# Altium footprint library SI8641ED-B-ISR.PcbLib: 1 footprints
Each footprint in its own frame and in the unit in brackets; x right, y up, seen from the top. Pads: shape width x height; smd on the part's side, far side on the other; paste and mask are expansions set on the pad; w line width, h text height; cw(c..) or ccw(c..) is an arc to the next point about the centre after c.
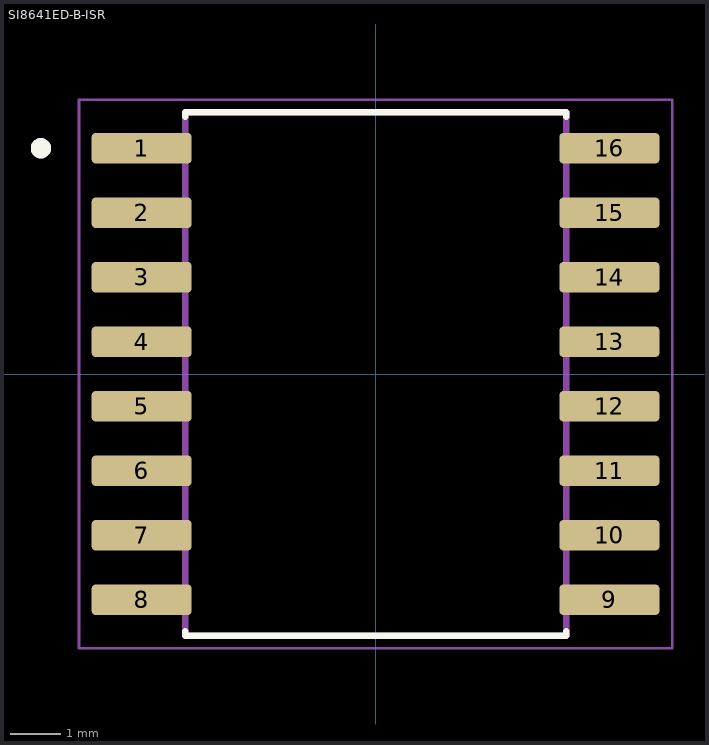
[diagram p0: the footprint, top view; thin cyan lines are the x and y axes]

## SI8641ED-B-ISR [mm]
pads (16):
  rrect25% 1.97x0.6 smd: 1(-4.605,4.445) 2(-4.605,3.175) 3(-4.605,1.905) 4(-4.605,0.635) 5(-4.605,-0.635) 6(-4.605,-1.905) 7(-4.605,-3.175) 8(-4.605,-4.445) 9(4.605,-4.445) 10(4.605,-3.175) 11(4.605,-1.905) 12(4.605,-0.635) 13(4.605,0.635) 14(4.605,1.905) 15(4.605,3.175) 16(4.605,4.445)
Top Overlay:
  circle w0.2: c-6.59,4.445 r0.1
  lines w0.127: -3.75,-5.065 -3.75,-5.15 3.75,-5.15 3.75,-5.065 ; -3.75,5.065 -3.75,5.15 3.75,5.15 3.75,5.065
Mechanical 13:
  circle w0.2: c-6.59,4.445 r0.1
  lines w0.127: -3.75,-5.15 -3.75,5.15 3.75,5.15 3.75,-5.15 -3.75,-5.15
Mechanical 15:
  lines w0.05: -5.84,-5.4 5.84,-5.4 5.84,5.4 -5.84,5.4 -5.84,-5.4
3D body "SI8641ED-B-ISR.STEP": height 2.65, standoff 0, extent -5.077,-5.119 5.223,5.181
